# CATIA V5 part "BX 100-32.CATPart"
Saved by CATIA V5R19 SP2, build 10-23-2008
Part number: BX 100-32
Bounding box of the stored display mesh (mm): x -18.951 to 18.951, y -18.952 to 18.952, z 0 to 167
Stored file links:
  C:\Users\Bora\Desktop\3D Katı model\BX serisi\BX 100\BX 100-32.CATPart
  C:\Program Files\Dassault Systemes\B19\intel_a\reffiles\standard\MetricThickPitch.txt
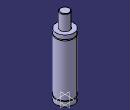
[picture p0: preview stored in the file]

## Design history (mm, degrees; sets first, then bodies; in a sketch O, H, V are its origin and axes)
Body1 (main body)
  Sketch1 on yz-plane, origin (0, 0, 0), H (0, 1, 0), V (0, 0, 1)
    point P1 (19, 125.5)
    line L1 (19, 134) -> (19, 125.5)
    point P4 (10, 166)
    line L2 (10, 166) -> (10, 134)
    point P6 (10, 166)
    arc A1 centre (9, 166) radius 1 from (10, 166) to (9, 167) ccw
    point P7 (19, 123.5)
    point P8 (19, 125.5)
    arc A2 centre (19, 124.5) radius 1 from (19, 125.5) to (19, 123.5) ccw
    point P9 (19, 11.5)
    point P10 (19, 123.5)
    line L3 (19, 123.5) -> (19, 11.5)
    point P11 (19, 9.5)
    point P12 (19, 11.5)
    arc A3 centre (19, 10.5) radius 1 from (19, 11.5) to (19, 9.5) ccw
    point P14 (19, 9.5)
    line L4 (19, 9.5) -> (19, 0)
    line L5 (9, 167) -> (0, 167)
    point P15 (0, 167)
    line L6 (10, 134) -> (19, 134)
    line L7 (19, 0) -> (0, 0)
    tangency: L5 A1
    coincidence: P15 V, P1 P8, P4 P6, P7 P10, P9 P12, P11 P14
    horizontal: L6 H, L7 H
  Shaft1: profile Sketch1, axis Sketch1.V, angle 360
  Sketch2 on face of Shaft1 from Sketch1.L7, origin (0, 0, 0), H (1, 0, 0), V (0, -1, 0)
    point P1 (9, 0)
    distance P1 V = 9
  Hole1: placed by Sketch2, at (9, 0, 0) direction (0, 0, 1), diameter 4.917, depth 6, threaded "M6", thread diameter 6, thread depth 6, pitch 1
  Sketch3 on face of Shaft1 from Sketch1.L7, origin (0, 0, 0), H (1, 0, 0), V (0, -1, 0)
    point P1 (-9, 0)
    distance P1 V = 9
  Hole2: placed by Sketch3, at (-9, 0, 0) direction (0, 0, 1), diameter 4.917, depth 6, threaded "M6", thread diameter 6, thread depth 6, pitch 1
